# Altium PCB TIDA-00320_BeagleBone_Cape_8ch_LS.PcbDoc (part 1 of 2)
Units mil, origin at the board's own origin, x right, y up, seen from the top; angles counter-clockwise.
Board outline 6250 x 2150 mil, 2 copper layers (Top Layer, Bottom Layer), stack 62 mil thick; 116 components, 142 nets, 397 pads, 432 vias.
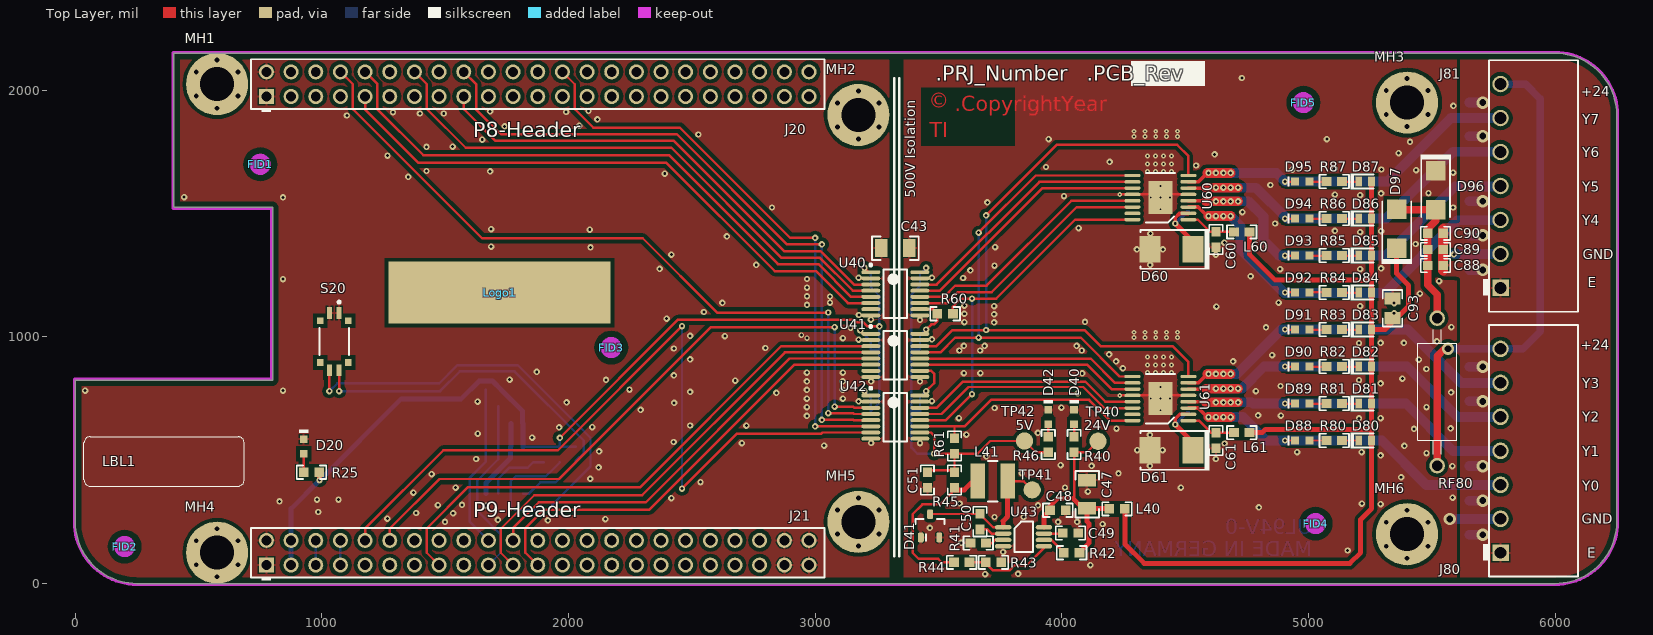
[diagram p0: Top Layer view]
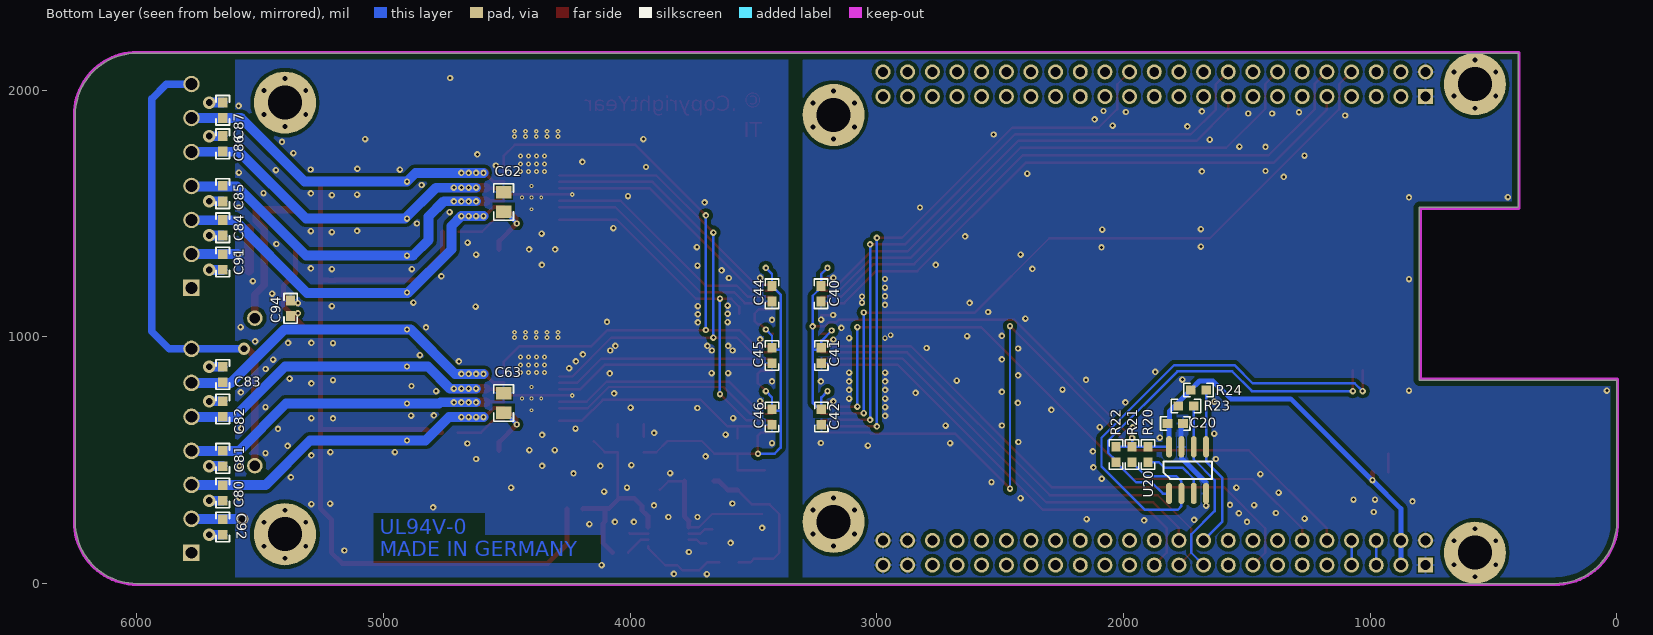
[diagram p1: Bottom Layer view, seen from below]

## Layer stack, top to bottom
Top Solder: solder mask 0.4, Solder Resist, Dk 3.5
Top Layer: signal copper 1.4
Dielectric1: core 59.2, FR-4, Dk 4.8
Bottom Layer: signal copper 1.4
Bottom Solder: solder mask 0.4, Solder Resist, Dk 3.5

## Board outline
250,0 cw(c250,250) 0,250 0,825 800,825 800,1525 400,1525 400,2150 6000,2150 cw(c6000,1900) 6250,1900 6250,250 cw(c6000,250) 6000,0

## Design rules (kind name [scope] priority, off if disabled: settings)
AcuteAngle [All] p1: minimum=3.00000000000000E+0001 checktracksonly=FALSE
AssemblyTestPointUsage [All] p1: valid=2
Clearance Clearance_BoardEdge_MountingHoles [OnCopper and InComponentClass('Mounting Holes') vs IsKeepOut] p1: gap=40
Clearance Clearance_BoardEdge_Poly [OnCopper and InPoly vs IsKeepOut] p2: gap=25
Clearance Clearance_BoardEdge [OnCopper and Not InComponentClass('Logo') and not InComponentClass('FiducialMark') and not InRegion(1000,500,4000,800) and Not IsKeepout vs IsKeepOut] p3: gap=24
Clearance Clearance_Poly [InPolygon] p4: gap=15
Clearance [All] p5: gap=7.87
ComponentClearance ComponentClearance_Shunt [InComponentClass('Header') vs InComponentClass('Shunt')] p1: gap=0 collisioncheckmode=3 verticalgap=0 showdistances=FALSE
ComponentClearance ComponentClearance_MountingHoles_FiducialMarks [InComponentClass('Mounting Holes') vs InComponentClass('FiducialMark')] p2: gap=50 collisioncheckmode=3 verticalgap=10 showdistances=FALSE
ComponentClearance ComponentClearance_Logo [InComponentClass('Logo')] p3: gap=50 collisioncheckmode=3 verticalgap=10 showdistances=FALSE
ComponentClearance ComponentClearance_ScrewToNut [(HasFootprint('NY PMS 440 0025 PH')) vs (HasFootprint('Keystone_1902C'))] p4: gap=5 collisioncheckmode=3 verticalgap=10 showdistances=FALSE
ComponentClearance ComponentClearance_MountingHoles [name like 'MH*'] p5: gap=0 collisioncheckmode=3 verticalgap=100000 showdistances=FALSE
ComponentClearance ComponentClearance_SmallPassives [HasFootprint('0201*') or HasFootprint('0402*') or HasFootprint('0508') or HasFootprint('0603*') or HasFootprint('0612') or HasFootprint('0805*') or HasFootprint('0815*') or HasFootprint('0830*') or HasFootprint('1206*') or HasFootprint('1210*') or HasFootprint('1808*') or HasFootprint('1812*') or HasFootprint('1825*') or HasFootprint('2010*') or HasFootprint('2220*') or HasFootprint('2225*') or HasFootprint('2512*') or HasFootprint('2728*') or HasFootprint('3518*') vs HasFootprint('0201*') or HasFootprint('0402*') or HasFootprint('0508') or HasFootprint('0603*') or HasFootprint('0612') or HasFootprint('0805*') or HasFootprint('0815*') or HasFootprint('0830*') or HasFootprint('1206*') or HasFootprint('1210*') or HasFootprint('1808*') or HasFootprint('1812*') or HasFootprint('1825*') or HasFootprint('2010*') or HasFootprint('2220*') or HasFootprint('2225*') or HasFootprint('2512*') or HasFootprint('2728*') or HasFootprint('3518*')] p6: gap=20 collisioncheckmode=3 verticalgap=10 showdistances=FALSE
ComponentClearance ComponentClearance_THtoSMT [IsThruComponent vs IsSMTComponent] p7: gap=90 collisioncheckmode=3 verticalgap=30 showdistances=FALSE
ComponentClearance ComponentClearance_THtoTH [IsThruComponent and not name like ('J8*') vs IsThruComponent and not name like ('J8*')] p8: gap=118.11 collisioncheckmode=3 verticalgap=30 showdistances=FALSE
ComponentClearance [All] p9: gap=38 collisioncheckmode=3 verticalgap=10 showdistances=FALSE
DiffPairsRouting [All] p1: maxlimit=100 minlimit=10 mostfreqgap=10 toplayer_minwidth=15 toplayer_maxwidth=15 toplayer_prefwidth=15 bottomlayer_minwidth=15 bottomlayer_maxwidth=15 bottomlayer_prefwidth=15 maxuncoupledlength=1000
FabricationTestPointUsage TestPointUsage [All] p1: valid=2 allowmultiple=FALSE
FabricationTestpoint Testpoint [All] p1: side=3 testpointundercomponent=TRUE minsize=40 maxsize=100 preferedsize=60 minholesize=0 maxholesize=40 preferedholesize=32 testpointgrid=1 allowsidetop=TRUE allowsidebottom=TRUE usegrid=TRUE gridtolerance=0.01
FanoutControl Fanout_LCC [IsLCC] p1: bgadir=Out bgaviamode=Centered fanoutstyle=Auto fanoutdirection=Alternating viagrid=1 // Fanout_LCC (Default Rule)
FanoutControl Fanout_BGA [IsBGA] p2: bgadir=Out bgaviamode=Centered fanoutstyle=Auto fanoutdirection=Alternating viagrid=1 // Fanout_BGA (Default Rule)
FanoutControl Fanout_Default [All] p4: bgadir=Out bgaviamode=Centered fanoutstyle=Auto fanoutdirection=Alternating viagrid=1 // Fanout_Default (Default Rule)
FanoutControl Fanout_Small [(CompPinCount < 5)] p5: bgadir=Out bgaviamode=Centered fanoutstyle=Auto fanoutdirection=OutThenIn viagrid=1 // Fanout_Small (Default Rule)
HoleSize [All] p1: absolutevalues=TRUE maxlimit=251 minlimit=7.6 maxpercent=80.000 minpercent=20.000
MinimumAnnularRing MinimumAnnularRing_InPoly [All] p1: minimumring=3
MinimumAnnularRing MinimumAnnularRing_ThermalPadVias [IsVia and InAnyComponent] p2: minimumring=3
MinimumAnnularRing [All] p3: minimumring=9
MinimumSolderMaskSliver MinimumSolderMaskSliver_Logo [InComponentClass('Logo') vs InComponentClass('Logo')] p1: minsoldermaskwidth=0.7
MinimumSolderMaskSliver [All] p2: minsoldermaskwidth=3.94
PlaneClearance [All] p1: clearance=10
PlaneConnect [All] p1: planeconnectstyle=Direct reliefexpansion=15 reliefentries=4 reliefconductorwidth=10 reliefairgap=5
PolygonConnect Polygon2Via [IsVia] p1: connectstyle=Direct reliefconductorwidth=10 reliefentries=4 polygonreliefangle="90 Angle" airgapwidth=10
PolygonConnect ThermalPolygonVia [IsVia AND (ViaDiameter = '50')] p2: connectstyle=Direct reliefconductorwidth=10 reliefentries=4 polygonreliefangle="90 Angle" airgapwidth=10
PolygonConnect ThermalPolygonPad [((ObjectKind = 'Pad') And (((Name Like 'U*') or (Name Like 'D*')) and (InComponentClass('Pg5 Cape Power Stages') or InComponentClass('Pg6 Cape Output')))) or ((ObjectKind = 'Pad') And (Name like 'U21*'))] p3: connectstyle=Direct reliefconductorwidth=10 reliefentries=4 polygonreliefangle="90 Angle" airgapwidth=10
PolygonConnect [All] p4: connectstyle=Relief reliefconductorwidth=10 reliefentries=4 polygonreliefangle="90 Angle" airgapwidth=5
RoutingVias ThermalPadVias [IsVia and InAnyComponent] p1: holewidth=7.87 width=19.68 viastyle="Through Hole" minholewidth=7.87 minwidth=10 maxholewidth=20 maxwidth=40
RoutingVias [All] p2: holewidth=16 width=34 viastyle="Through Hole" minholewidth=7.87 minwidth=20 maxholewidth=40 maxwidth=65
SMDToCorner [All] p1: distance=0
ShortCircuit ShortCircuit_MH_Via [name like 'MH*' vs IsVia] p1: allowed=TRUE
ShortCircuit [All] p2: allowed=FALSE
SilkToSilkClearance [All] p1: silktosilkclearance=0
SilkToSolderMaskClearance SilkscreenOverComponentPads [IsPad] p1: minsilkscreentomaskgap=0 clearancetoexposedcopper=TRUE
SolderMaskExpansion [All] p1: expansion=1.97
UnpouredPolygon [All] p1: allowunpoured=FALSE
Width [All] p1: maxlimit=100 minlimit=6 preferedwidth=10 checkconnectedcopper=TRUE
13 further rules are at their usual default settings.

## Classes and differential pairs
component class "Pg6 Cape Output": C80 C81 C82 C83 C84 C85 C86 C87 C88 C89 C90 C91 C92 C93 C94 D80 D81 D82 D83 D84 D85 D86 D87 D88 D89 D90 D91 D92 D93 D94 D95 D96 D97 J80 J81 R80 R81 R82 R83 R84 R85 R86 R87 RF80
component class "Pg5 Cape Power Stages": C60 C61 C62 C63 D60 D61 L60 L61 R60 R61 U60 U61
component class "Pg4 Cape Power Supply": C40 C41 C42 C43 C44 C45 C46 C47 C48 C49 C50 C51 D40 D41 D42 L40 L41 R40 R41 R42 R43 R44 R45 R46 TP40 TP41 TP42 U40 U41 U42 U43
component class Logo: Logo1
component class "Pg7 Hardware": FID1 FID2 FID3 FID4 FID5 LBL1 Logo1 MH1 MH2 MH3 MH4 MH5 MH6 ZZ1 ZZ2 ZZ3 ZZ4
component class FiducialMark: FID1 FID2 FID3 FID4 FID5
component class AssemblyNote: ZZ1 ZZ2 ZZ3 ZZ4
component class Label: LBL1
component class "Pg3 BB Connectors": C20 D20 J20 J21 R20 R21 R22 R23 R24 R25 S20 U20

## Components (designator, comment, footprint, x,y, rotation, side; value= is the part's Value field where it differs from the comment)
C20 "C0603C104K5RACTU" 0603 1790,649 r180 bottom
C40 "C0603C104K5RACTU" 0603 3226,1175 r270 bottom
C41 "C0603C104K5RACTU" 0603 3225,925 r270 bottom
C42 "C0603C104K5RACTU" 0603 3225,675 r270 bottom
C43 "202R18W102KV4E" 1206 3325,1360 r180 top
C44 "C0603C104K5RACTU" 0603 3425,1175 r270 bottom
C45 "C0603C104K5RACTU" 0603 3425,925 r270 bottom
C46 "C0603C104K5RACTU" 0603 3425,675 r270 bottom
C47 "C3216X7R1H105K" 1206 4103,362 r90 top
C48 "C0603C104K5RACTU" 0603 3984,297 r0 top
C49 "C0603C104K5RACTU" 0603 4035,205 r180 top
C50 "C0603C223K5RACTU" 0603 3668,251 r90 top
C51 "C0603C475K8PACTU" 0603 3455,420 r270 top
C60 "C0603C104K5RACTU" 0603 4625,1395 r270 top
C61 "C0603C104K5RACTU" 0603 4625,580 r270 top
C62 "CL21B104KCFSFNE" 0805_HV 4513.65,1547.09 r90 bottom
C63 "CL21B104KCFSFNE" 0805_HV 4513.65,732.09 r90 bottom
C80 "C1608X7R2A103M" 0603 5652,367.45 r270 bottom
C81 "C1608X7R2A103M" 0603 5652,507.45 r270 bottom
C82 "C1608X7R2A103M" 0603 5652,707.45 r90 bottom
C83 "C1608X7R2A103M" 0603 5652,847.45 r90 bottom
C84 "C1608X7R2A103M" 0603 5652,1443 r270 bottom
C85 "C1608X7R2A103M" 0603 5652,1581 r270 bottom
C86 "C1608X7R2A103M" 0603 5652,1783 r90 bottom
C87 "C1608X7R2A103M" 0603 5652,1919 r90 bottom
C88 "C1608X8R2A472K" 0603 5515,1290 r0 top
C89 "C1608X8R2A472K" 0603 5515,1355 r0 top
C90 "C1608X8R2A472K" 0603 5515,1420 r0 top
C91 "C1608X8R2A472K" 0603 5652,1304 r270 bottom
C92 "C1608X8R2A472K" 0603 5652,229 r270 bottom
C93 "CL21B105KBFNNNE" 0805_HV 5341,1116 r90 top
C94 "C0603C104K5RACTU" 0603 5377,1116 r90 bottom
D20 "LTST-C190KGKT" LED_LTST-C190_G 926,556 r90 top
D40 "LTST-C190KGKT" LED_LTST-C190_G 4050,675 r90 top
D41 "BAV70-V" SOT-23 3466,234 r90 top
D42 "LTST-C190KGKT" LED_LTST-C190_G 3945,675 r90 top
D60 "SMBJ48A-13-F" SMB 4444.51,1355 r180 top
D61 "SMBJ48A-13-F" SMB 4444.51,540 r180 top
D80 "CD0603-S0180" Diode_0603 5230,580 r0 top
D81 "CD0603-S0180" Diode_0603 5230,730 r0 top
D82 "CD0603-S0180" Diode_0603 5230,880 r0 top
D83 "CD0603-S0180" Diode_0603 5230,1030 r0 top
D84 "CD0603-S0180" Diode_0603 5230,1180 r0 top
D85 "CD0603-S0180" Diode_0603 5230,1330 r0 top
D86 "CD0603-S0180" Diode_0603 5230,1480 r0 top
D87 "CD0603-S0180" Diode_0603 5230,1630 r0 top
D88 "LB Q39G-L2N2-35-1" "LB Q39G_BLUE" 4974.94,580 r180 top
D89 "LB Q39G-L2N2-35-1" "LB Q39G_BLUE" 4974.94,730 r180 top
D90 "LB Q39G-L2N2-35-1" "LB Q39G_BLUE" 4974.97,880.03 r180 top
D91 "LB Q39G-L2N2-35-1" "LB Q39G_BLUE" 4974.94,1029.97 r180 top
D92 "LB Q39G-L2N2-35-1" "LB Q39G_BLUE" 4974.94,1180.29 r180 top
D93 "LB Q39G-L2N2-35-1" "LB Q39G_BLUE" 4975,1330 r180 top
D94 "LB Q39G-L2N2-35-1" "LB Q39G_BLUE" 4974.94,1479.99 r180 top
D95 "LB Q39G-L2N2-35-1" "LB Q39G_BLUE" 4975,1630 r180 top
D96 "SMAJ33CA" SMA 5516,1595 r270 top
D97 "MRA4003T3G" SMA 5358,1439 r90 top
FID1 "Fiducial" Fiducial10-20#1 750,1700 r0 top
FID2 "Fiducial" Fiducial10-20#1 200,150 r0 top
FID3 "Fiducial" Fiducial10-20#1 2173,957 r0 top
FID4 "Fiducial" Fiducial10-20#2 5029,243 r0 top
FID5 "Fiducial" Fiducial10-20#2 4980,1950 r0 top
J20 "SSHQ-123-D-08-F-LF" Major_SSHQ-123-D-08 1875,2025 r0 top
J21 "SSHQ-123-D-08-F-LF" Major_SSHQ-123-D-08 1875,125 r0 top
J80 "1844265" Phoenix_1844265 5779,538 r90 top
J81 "1844265" Phoenix_1844265 5779,1612 r90 top
L40 "BLM18KG601SN1D" 0603 4224,303 r180 top
L41 "SRN4026-680M" SRN4026 3720,415 r180 top
L60 "BLM18KG601SN1D" 0603 4730,1426 r180 top
L61 "BLM18KG601SN1D" 0603 4730,612 r180 top
LBL1 "Size: 0.65\" x 0.20 \"" Label_650x200 360,495 r0 top
Logo1 "Texas Instruments" TI_Stacked_SolderMask_Small 1720,1180 r0 top
MH1 "MTG_Pads" MTGP_4-40_PanHead 575,2025 r0 top
MH2 "MTG_Pads" MTGP_4-40_PanHead 3175,1900 r0 top
MH3 "MTG_Pads" MTGP_4-40_PanHead 5400,1950 r0 top
MH4 "MTG_Pads" MTGP_4-40_PanHead 575,125 r0 top
MH5 "MTG_Pads" MTGP_4-40_PanHead 3175,250 r0 top
MH6 "MTG_Pads" MTGP_4-40_PanHead 5400,200 r0 top
R20 "CRCW06035K62FKEA" 0603 1900,523.35 r90 bottom
R21 "CRCW06035K62FKEA" 0603 1965,523.35 r90 bottom
R22 "CRCW06035K62FKEA" 0603 2030,523.35 r90 bottom
R23 "CRCW06035K62FKEA" 0603 1746,720 r0 bottom
R24 "CRCW06035K62FKEA" 0603 1696,785 r0 bottom
R25 "CRCW0603453RFKEA" 0603 958,451 r0 top
R40 "CRCW06037K50FKEA" 0603 4050,564 r270 top
R41 "CRCW060386K6FKEA" 0603 3661,164 r0 top
R42 "CRCW060366K5FKEA" 0603 4040,125 r0 top
R43 "CRCW06032K00FKEA" 0603 3723,86 r180 top
R44 "CRCW06032K00FKEA" 0603 3594,86 r0 top
R45 "CRCW06031R00FKEA" 0603 3565,420 r90 top
R46 "CRCW06031K21FKEA" 0603 3945,564 r90 top
R60 "CRCW06032K00FKEA" 0603 3527,1094 r0 top
R61 "CRCW06032K00FKEA" 0603 3565,558 r90 top
R80 "CRCW060310K0FKEA" 0603 5105,580 r0 top
R81 "CRCW060310K0FKEA" 0603 5105,730 r0 top
R82 "CRCW060310K0FKEA" 0603 5105,880 r0 top
R83 "CRCW060310K0FKEA" 0603 5105,1030 r0 top
R84 "CRCW060310K0FKEA" 0603 5105,1180 r0 top
R85 "CRCW060310K0FKEA" 0603 5105,1330 r0 top
R86 "CRCW060310K0FKEA" 0603 5105,1480 r0 top
R87 "CRCW060310K0FKEA" 0603 5105,1630 r0 top
RF80 "47 Ohm" EMC2 5522,777 r270 top
S20 "CVS-02TB" SW_CVS-02B 1050,981 r270 top
TP40 "Pogo Pad" PogoPad 4147,577 r90 top
TP41 "Pogo Pad" PogoPad 3880,380 r90 top
TP42 "Pogo Pad" PogoPad 3849,578 r90 top
U20 "AT24C02D-SSHM-T" SOIC-8 1740,460 r90 bottom
U40 "ISO7140CCDBQ" DBQ0016A_N 3325,1175 r0 top
U41 "ISO7140CCDBQ" DBQ0016A_N 3325,925 r0 top
U42 "ISO7142CCDBQ" DBQ0016A_N 3325,675 r0 top
U43 "SM72485MM/NOPB" DGK0008A_N 3845,189.68 r0 top
U60 "DRV8803PWPR" PWP0016D_N 4400,1565 r180 top
U61 "DRV8803PWPR" PWP0016D_N 4400,750 r180 top
ZZ1 "This Assembly Note is for PCB labels only" AssemblyNoteLabel 185,3938 r0 top
ZZ2 "These assemblies are ESD sensitive, ESD precautions shall be observed." AssemblyNote 185,3829.11 r0 top
ZZ3 "These assemblies must be clean and free from flux and all contaminants. Use of no clean flux is not acceptable." AssemblyNote 185,3740.56 r0 top
ZZ4 "These assemblies must comply with workmanship standards IPC-A-610 Class 2, unless otherwise specified." AssemblyNote 185,3652 r0 top

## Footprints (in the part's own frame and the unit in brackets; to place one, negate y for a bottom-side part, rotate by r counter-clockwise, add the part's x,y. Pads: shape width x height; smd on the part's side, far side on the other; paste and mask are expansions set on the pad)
0603 [mm] "0603 from SM-752 data"
  rect 1x0.95 smd: 1(-0.8,0) 2(0.8,0)
  silkscreen extent -1.52,-0.69 1.52,0.69, body extent -0.87,-0.47 0.87,0.47, height 0.85
0805_HV [mil] "0805 with 30mil clearance between pads"
  rect 50x63 smd: 1(-40,0) 2(40,0)
  silkscreen extent -74,-40 74,40, body extent -43,-29 43,29, height 43
1206 [mm] "1206 from SM-752 data"
  rect 1.3x1.85 smd: 1(-1.45,0) 2(1.45,0)
  silkscreen extent -2.4,-1.21 2.4,1.21, body extent -1.7,-0.9 1.7,0.9, height 1.35
AssemblyNote [mil] "Assembly Note"
AssemblyNoteLabel [mil] "Assembly Note for PCB Labels"
DBQ0016A_N [mm] "SOP, 16-Leads, Body 4.9x3.9mm, Pitch 0.635mm, IPC Medium Density"
  oval 1.95x0.4 smd: 1(-2.525,2.222) 2(-2.525,1.587) 3(-2.525,0.953) 4(-2.525,0.318) 5(-2.525,-0.318) 6(-2.525,-0.953) 7(-2.525,-1.587) 8(-2.525,-2.222) 9(2.525,-2.222) 10(2.525,-1.587) 11(2.525,-0.953) 12(2.525,-0.318) 13(2.525,0.318) 14(2.525,0.953) 15(2.525,1.587) 16(2.525,2.222)
  silkscreen extent -2.65,-2.5 1.2,3.1, body extent -1.99,-2.5 2,2.5, height 1.76
DGK0008A_N [mm] "TSOP, 8-Leads, Body 3x3mm, Pitch 0.65mm, IPC Medium Density"
  oval 1.7x0.45 smd mask+0.05: 1(-2.1,0.975) 2(-2.1,0.325) 3(-2.1,-0.325) 4(-2.1,-0.975) 5(2.1,-0.975) 6(2.1,-0.325) 7(2.1,0.325) 8(2.1,0.975)
  silkscreen extent -0.95,-1.55 0.95,1.55, body extent -2.45,-1.5 2.45,1.5, height 0.94
Diode_0603 [mm] "Based on Bourns recommended land pattern Rev 10/09"
  rect 0.7x1 smd: 1(-0.65,0) 2(0.65,0)
  silkscreen extent -1.5,-0.8 0.9,0.8, body extent -0.9,-0.5 0.9,0.5, height 0.85
EMC2 [mm] "Welwyn"
  round 1.6 hole 1.1: 1(-7.6,0) 2(7.6,0)
  silkscreen extent -6.42,-2 6.42,2, body extent -8.02,-2 8.02,2, height 3.98
Fiducial10-20#1 [mm]
  round 1 smd paste-0.5 mask+0.5: 1(0,0)
  Top Layer keep-out circle w1.178: c0,0 r0.5
Fiducial10-20#2 [mm]
  round 1 smd mask+0.5: 1(0,0)
  Top Layer keep-out circle w1.178: c0,0 r0.5
Label_650x200 [mil] "Thermal Transfer Label"
  round 1 on Mech13: 0(0,0)
  silkscreen extent -325,-100 325,100, body extent -326,-101 326,101, height 1
"LB Q39G_BLUE" [mm] "OSRAM"
  rect 0.8x0.8 smd: 1(-0.75,0) 2(0.75,0)
  silkscreen extent 1.3,-0.5 1.52,0.5, body extent -0.85,-0.45 0.85,0.45, height 0.4
LED_LTST-C190_G [mm] "Lite-On"
  rect 0.8x0.8 smd: 1(-0.75,0) 2(0.75,0)
  silkscreen extent 1.37,-0.5 1.75,0.5, body extent -0.85,-0.45 0.85,0.45, height 0.9
Major_SSHQ-123-D-08 [mm] "Female Connector, 2.54mm, 23x2, TH"
  rect 1.55x1.55 hole 1.02: 1(-27.94,-1.27)
  round 1.55 hole 1.02: 2(-27.94,1.27) 3(-25.4,-1.27) 4(-25.4,1.27) 5(-22.86,-1.27) 6(-22.86,1.27) 7(-20.32,-1.27) 8(-20.32,1.27) 9(-17.78,-1.27) 10(-17.78,1.27) 11(-15.24,-1.27) 12(-15.24,1.27) 13(-12.7,-1.27) 14(-12.7,1.27) 15(-10.16,-1.27) 16(-10.16,1.27) 17(-7.62,-1.27) 18(-7.62,1.27) 19(-5.08,-1.27) 20(-5.08,1.27) 21(-2.54,-1.27) 22(-2.54,1.27) 23(0,-1.27) 24(0,1.27) 25(2.54,-1.27) 26(2.54,1.27) 27(5.08,-1.27) 28(5.08,1.27) 29(7.62,-1.27) 30(7.62,1.27) 31(10.16,-1.27) 32(10.16,1.27) 33(12.7,-1.27) 34(12.7,1.27) 35(15.24,-1.27) 36(15.24,1.27) 37(17.78,-1.27) 38(17.78,1.27) 39(20.32,-1.27) 40(20.32,1.27) 41(22.86,-1.27) 42(22.86,1.27) 43(25.4,-1.27) 44(25.4,1.27) 45(27.94,-1.27) 46(27.94,1.27)
  silkscreen extent -29.53,-2.85 29.53,2.57, body extent -29.46,-2.51 29.46,2.51, height 8.51
MTGP_4-40_PanHead [mm] "4-40 Mounting Hole, Plated, for Pan Head"
  round 6.4 hole 3.5: 1(0,0)
Phoenix_1844265 [mm] "TH, 7-Leads, Body 9.2x25.9, Pitch 3.5mm"
  rect 1.7x1.7 hole 1.2: 1(-10.5,0)
  round 1.7 hole 1.2: 2(-7,0) 3(-3.5,0) 4(0,0) 5(3.5,0) 6(7,0) 7(10.5,0)
  silkscreen extent -12.95,-8 12.95,1.8, body extent -12.95,-8 12.95,1.2, height 7.25
PogoPad [mil] "No Solder Paste"
  round 70 smd paste-35: 1(0,0)
PWP0016D_N [mm] "TSOP, 16-Leads, Body 5x4.4mm, Pitch 0.65mm, Exposed Pad, IPC Medium Density"
  oval 1.65x0.35 smd: 1(-2.875,2.275) 2(-2.875,1.625) 3(-2.875,0.975) 4(-2.875,0.325) 5(-2.875,-0.325) 6(-2.875,-0.975) 7(-2.875,-1.625) 8(-2.875,-2.275) 9(2.875,-2.275) 10(2.875,-1.625) 11(2.875,-0.975) 12(2.875,-0.325) 13(2.875,0.325) 14(2.875,0.975) 15(2.875,1.625) 16(2.875,2.275)
  rect 2.46x3.4 smd paste-1.5: 17(0,0)
  silkscreen extent -1.5,-2.55 1.5,2.55, body extent -3.21,-2.5 3.21,2.5, height 0.99
SMA [mm] "Molded Diode, 2-Leads, Body 4.3x2.6mm, IPC Medium Density, based on OnSemi component dimensions and land pattern"
  rect 2x2 smd: 1(-2,0) 2(2,0)
  silkscreen extent -3.66,-1.57 2.79,1.57, body extent -2.6,-1.3 2.6,1.3, height 2.42
SMB [mil] "Molded Diode, 2-Leads, Body 5.4x3.6mm, IPC Medium Density, based on OnSemi component dimensions"
  rect 85x107.99 smd: 1(-87.01,0) 2(87.01,0)
  silkscreen extent -155,-82 125,82, body extent -106,-71 106,71, height 91
SOIC-8 [mm] "duplicate of SO-8.  SOIC, 8-Leads, Body 5.0x4.0mm (max), Pitch 1.27mm, IPC Medium Density"
  oval 2.2x0.6 smd: 1(-2.4,1.905) 2(-2.4,0.635) 3(-2.4,-0.635) 4(-2.4,-1.905) 5(2.4,-1.905) 6(2.4,-0.635) 7(2.4,0.635) 8(2.4,1.905)
  silkscreen extent -0.9,-2.5 0.9,2.5, body extent -3,-2.45 3,2.45, height 1.63
SOT-23 [mm] "SOT23, 3-Leads, Body 2.9x1.3mm, Pitch 0.95mm, Lead Span 2.5mm, IPC Medium Density"
  rrect50% 1x0.6 smd: 1(-1.2,0.95) 2(-1.2,-0.95) 3(1.2,0)
  silkscreen extent -1.62,-1.5 0.7,1.5, body extent -1.16,-1.45 1.21,1.45, height 1
SRN4026 [mm] "SMD, 2-Leads, Body 4.2x4.2mm"
  rect 1.5x3.6 smd: 1(-1.525,0) 2(1.525,0)
  silkscreen extent -0.5,-2.1 0.5,2.1, body extent -2.1,-2.1 2.1,2.1, height 2.5
SW_CVS-02B [mm] "Copal Electronics"
  rect 1.2x0.5 smd: 1(-2.95,0.5) 2(-2.95,-0.5) 3(2.95,-0.5) 4(2.95,0.5)
  rect 0.7x0.7 smd: M1(-2.15,1.45) M2(-2.15,-1.45) M3(2.15,-1.45) M4(2.15,1.45)
  silkscreen extent -4.19,-1.5 1.4,1.5, body extent -2.15,-1.5 2.15,1.5, height 1.45
TI_Stacked_SolderMask_Small [mil]
  rect 900x250 smd paste-125 mask-125: 0(0,0)

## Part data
C20 C40 C41 C42 C44 C45 C46 C49 C60 C61: "CAP, CERM, 0.1 µF, 50 V, +/- 10%, X7R, 0603"
C43: "CAP, CERM, 1000pF, 2KV 10% X7R 1206"
C47: "CAP, CERM, 1uF, 50V, +/-10%, X7R, 1206"
C48 C94: "CAP, CERM, 0.1uF, 50V, +/-10%, X7R, 0603"
C50: "CAP, CERM, 0.022 µF, 50 V, +/- 10%, X7R, 0603"
C51: "CAP, CERM, 4.7 µF, 10 V, +/- 10%, X5R, 0603"
C62 C63: "CAP, CERM, 0.1 µF, 100 V, +/- 10%, X7R, 0805"
C80 C81 C82 C83 C84 C85 C86 C87: "CAP, CERM, 0.01 µF, 100 V, +/- 20%, X7R, 0603"
C88 C89 C90 C91 C92: "CAP, CERM, 4700 pF, 100 V, +/- 10%, X8R, 0603"
C93: "CAP, CERM, 1 µF, 50 V, +/- 10%, X7R, 0805"
D20 D40 D42: "LED, Green, SMD"
D41: "Diode, Switching, 70 V, 0.25 A, SOT-23"
D60 D61: "Diode, TVS, Uni, 48V, 600W, SMB"
D80 D81 D82 D83 D84 D85 D86 D87: "Diode, Switching, 90V, 0.1A, 0603 Diode"
D88 D89 D90 D91 D92 D93 D94 D95: "LED, Blue, SMD"
D96: "Diode, TVS, Bi, 33V, 400W, SMA"
D97: "Diode, Standard Recovery Rectifier, 300V, 1A, SMA"
FID1 FID2 FID3 FID4 FID5: "Fiducial mark.  There is nothing to buy or mount."
J20 J21: "Female Connector, 2.54mm, 23x2, TH"
J80 J81: "Header (Shrouded), 3.5 mm, 7x1, R/A, TH"
L40 L60 L61: "Ferrite Bead, 600 ohm @ 100 MHz, 1.3 A, 0603"
L41: "Inductor, Wirewound, Ferrite, 68uH, 0.35A, 0.852 ohm, SMD"
LBL1: library part THT-14-423-10, "Thermal Transfer Printable Labels, 0.650\" W x 0.200\" H - 10,000 per roll"
Logo1: library part TI_Logo, "Texas Instrument Corporate Signature"
MH1 MH2 MH3 MH4 MH5 MH6: library part "Mounting Hole (Imperial) with Pads", "PCB Mounting Hole"
R20 R21 R22 R23 R24: "RES, 5.62 k, 1%, 0.1 W, 0603"
R25: "RES, 453, 1%, 0.1 W, 0603"
R40: "RES, 7.50 k, 1%, 0.1 W, 0603"
R41: "RES, 86.6k ohm, 1%, 0.1W, 0603"
R42: "RES, 66.5k ohm, 1%, 0.1W, 0603"
R43 R44 R60 R61: "RES, 2.00 k, 1%, 0.1 W, 0603"
R45: "RES, 1.00, 1%, 0.1 W, 0603"
R46: "RES, 1.21 k, 1%, 0.1 W, 0603"
R80 R81 R82 R83 R84 R85 R86 R87: "RES, 10.0k ohm, 1%, 0.1W, 0603"
RF80: library part EMC2-47RKI, "RES, 47 ohm, 10%, 2W, Fusible, TH"
S20: "DIP Switch, SPST, 2Pos, Slide, SMT"
TP40 TP41 TP42: library part PogoPad, "Pad for Pogo Pin Connector"
U20: "I2C-Compatible (2-wire) Serial EEPROM 2-Kbit (256 x 8), SOIC-8"
U40 U41: "4242-VPK Small-Footprint and Low-Power Quad Channels Digital Isolators, DBQ0016A"
U42: "4242-V PK Small-Footprint and Low-Power Quad Channel Digital Isolator, DBQ0016A"
U43: "SolarMagic 100V, 150 mA Constant On-Time Buck Switching Regulator, DGK0008A"
U60 U61: "Quad Low-Side Driver IC, PWP0016D"
ZZ1: library part AssemblyNoteLabel
ZZ2 ZZ3 ZZ4: library part AssemblyNote

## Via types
v1: diameter 26, hole 12, Top Layer to Bottom Layer, tented both sides, 318 vias
v2: diameter 20, hole 8, Top Layer to Bottom Layer, tented both sides, 46 vias
v3: diameter 39.37, hole 19.68, Top Layer to Bottom Layer, 36 vias
v4: diameter 50, hole 28, Top Layer to Bottom Layer, tented both sides, 11 vias
v5: diameter 15.75, hole 7.87, Top Layer to Bottom Layer, 10 vias
v6: diameter 26, hole 12, Top Layer to Bottom Layer, 8 vias
v7: diameter 22, hole 12, Top Layer to Bottom Layer, tented both sides, 2 vias
v8: diameter 50, hole 28, Top Layer to Bottom Layer, 1 vias

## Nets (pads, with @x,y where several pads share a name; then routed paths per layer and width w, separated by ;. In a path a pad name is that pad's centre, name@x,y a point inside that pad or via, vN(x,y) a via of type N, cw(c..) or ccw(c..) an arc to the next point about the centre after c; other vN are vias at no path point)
24V_EXT: J80.7 J81.7 RF80.2 | length 2032.2
  Top Layer w30: RF80.2@5522,477.79 5522,922.19 5551.81,952 v8(5565.9,952)
  Bottom Layer w30: v8(5565.9,952) 5870,952 5940,1022 5940,1965 5881,2024 J81.7@5779,2024
+5V_ISO: C44.1 C45.1 C46.1 C51.1 R45.2 R46.1 R60.1 R61.1 TP42.1 U40.10 U40.16 U41.10 U41.16 U42.10 U42.16 | length 2241.2
  Top Layer w10: U41.16@3422.5,1012.5 U41.16@3424.41,1012.5 ; U42.10@3424.41,612.5 3469.5,612.5 3482,600 v1(3482,526.38) R61.1@3565,526.38 ; U41.10@3424.41,862.5 3470.5,862.5 3482,851 3482,812 v1(3450,780) ; U40.10@3424.41,1112.5 3477,1112.5 R60.1@3495.5,1094 3495.5,1064.86 3481.82,1051.18 3471.18,1051.18 v1(3450,1030) ; C51.1@3455,460 3565,460 R61.1@3565,526.38 ; R46.1@3945,532.5 3894.5,532.5 TP42.1@3849,578 3710,578 3658.38,526.38 R61.1@3565,526.38
  Bottom Layer w10: 3394,700 3426.38,700 3425,698.62 3425,755 v1(3450,780) ; v1(3450,1030) 3425,1005 3425,948.62 3390,948.62 ; v1(3450,1280) 3425,1255 C44.1@3425,1206.5 3390,1171.5 3390,948.62 ; v1(3482,526.38) 3414.62,526.38 3390,551 3390,948.62
+24V_EMI1: C60.1 L60.2 U60.1 | length 202.1
  Top Layer w10: U60.1@4513.19,1475.43 4551.31,1475.43 4600.24,1426.5 C60.1@4625,1426.5 L60.2@4695,1426.5
+24V_EMI2: C61.1 L61.2 U61.1 | length 205.4
  Top Layer w10: U61.1@4513.19,660.43 4556.01,660.43 4604.44,612 L61.2@4698.5,612
+24V_FIELD: C93.1 C94.1 D80.2 D81.2 D82.2 D83.2 D84.2 D85.2 D86.2 D87.2 D97.1 L40.1 L60.1 L61.1 | length 4239.9
  Top Layer w20: L40.1@4255.5,303 4255.5,160.5 4334,82 5168,82 5211.51,125.51 5211.51,259.51 5255.59,303.59 D80.2@5255.59,580 D81.2@5255.59,730 D82.2@5255.59,880 D83.2@5255.59,1030 ; L60.1@4761.5,1426 4761.5,1333.5 4865,1230 5196.34,1230 5197.21,1229.13 5222.79,1229.13 5223.66,1230 5255.59,1230 ; L61.1@4764.5,612 4813,612 4826,625 5251.46,625 ; D87.2@5255.59,1630 D86.2@5255.59,1480 D85.2@5255.59,1330 D84.2@5255.59,1180 D83.2@5255.59,1030 ; D97.1@5358,1360.26 5358,1257 5406,1209 5406,1123.91 5341,1058.91 5312.09,1030 D83.2@5255.59,1030
  other v1: 5348,1096
/FAULT0: R61.2 U42.11 U61.16 | length 989
  Top Layer w10: U42.11@3424.41,637.5 3605.5,637.5 3713,745 4110.87,745 4195.43,660.43 U61.16@4286.81,660.43 ; R61.2@3565,589.5 3565,636.5
/FAULT1: R60.2 U42.12 U60.16 | length 1545.3
  Top Layer w10: U42.12@3424.41,662.5 3530.5,662.5 v1(3636,768) ; R60.2@3558.5,1094 3558.5,1122.5 3591,1155 v1(3636,1155) 3734,1155 4054.43,1475.43 U60.16@4286.81,1475.43
  Bottom Layer w10: v1(3636,768) v1(3636,1155)
AIN0: J21.39
AIN1: J21.40
AIN2: J21.37
AIN3: J21.38
AIN4: J21.33
AIN5: J21.36
AIN6: J21.35
CLKOUT2: J21.41
DGND: C20.2 C40.2 C41.2 C42.2 C43.2 D20.2 J20.1 J20.2 J21.1 J21.2 J21.43 J21.44 J21.45 J21.46 S20.1 S20.2 U20.4 U20.7 U40.2 U40.8 U41.2 U41.8 U42.2 U42.8 | length 541.1
  Top Layer w10: v1(3176,739) 3177.5,737.5 U42.2@3225.59,737.5 ; v1(3176,989) 3177.5,987.5 U41.2@3225.59,987.5 ; v1(3176,1240) 3178.5,1237.5 U40.2@3225.59,1237.5 ; v1(3177.36,1089) 3178.86,1087.5 U40.8@3225.59,1087.5 3225.59,1070.41 v1(3226,1070)
  Bottom Layer w20: U20.4@1665,365.51 1665,409 1765,509 U20.7@1765,554.49 ; U20.7@1766.38,555.87 C20.2@1766.38,649
  other v1: 1499,250 1916,256 1713,258 2149,261 1265,263 1532,285 1382,286 985,290 1665,316 1470,318 1568,319 828,333 980,340 1067,340 2417,346 1371,369 1542,389 2535,411 2088,425 1445,444 2122,471 1625,505 2124,536 3036,559 2703,569 3227,570 2426,574 1852,592 1631.73,607.64 1962,633 2096,634 2721,640 2493,641 2966,680 2292,704 2966,715 2428,733 1992,735 1631,738 2966,750 3112,750 2843,773 2493,777 40,782 842,782 2966,785 3112,785 2247,786 2966,820 3112,820 3227,820 2676,823 2152,826 1761,827 2427,844 2966,855 3112,855 1871,858 2493,909 2427,953 2798,955 3112,995 2634,1003 2493,1004 3144,1037 2398,1074 2549,1101 2967,1130 2624,1138 3060,1139 3060,1164 2967,1165 2967,1200 842,1234 2967,1235 2369,1276 2761,1292 2417,1334 2089,1363 1686,1366 2642,1408 2086,1435 1686,1437 2825,1525 842,1566 441,1567 1350,1649 2390,1662 1682,1671 1424,1673 1266,1735 1424,1771 1530,1772 1650,1800 2526,1821 1741,1854 2044,1857 2117,1882 1101,1898 1397,1906 1494,1906 1288,1911 1990,1912 1682,1915 2081,1916
  other v7: 2967,995 2944,1007
EHRPWM1A: J21.14
EHRPWM1B: J21.16
EHRPWM2A: J20.19
EHRPWM2B: J20.13
GND_EARTH: C80.2 C81.2 C82.2 C83.2 C84.2 C85.2 C86.2 C87.2 C88.2 C89.2 C90.2 C91.2 C92.2 J80.1 J81.1 | length 715.3
  Top Layer w40: 5546.5,1269 C89.2@5546.5,1355 C90.2@5546.5,1437
  Bottom Layer w40: C80.2@5652,335.95 v4(5707,336) ; C87.2@5652,1950 v4(5707,1950) ; C81.2@5652,475.95 v4(5707,476) ; C82.2@5652.06,739 v4(5707,739) ; C83.2@5652.06,879 v4(5707,879) ; C92.2@5652.5,198 v4(5707,198) ; C91.2@5652.5,1272 v4(5707,1272) ; C84.2@5652.5,1412 v4(5707,1412) ; C85.2@5652.5,1550 v4(5707,1550) ; C86.2@5652.5,1814 v4(5707,1814)
GND_ISO: C43.1 C44.2 C45.2 C46.2 C47.2 C48.2 C49.1 C51.2 C60.2 C61.2 C62.2 C63.2 C91.1 C92.1 C93.2 C94.2 D40.2 D41.1 D41.2 D42.2 D60.2 D61.2 D96.1 J80.2 J81.2 R41.1 R43.1 U40.9 U40.15 U41.9 U41.15 U42.9 U42.15 U43.4 U60.5 U60.12 U60.17 U61.5 U61.12 U61.17 | length 950
  Top Layer w10: v2@4235,762.8 U61.5@4513.19,762.8 ; v2@4235,1577.8 U60.5@4513.19,1577.8
  Bottom Layer w40: v4@5573,262.41 J80.2@5779,262.41 ; v1@5591.41,1336.41 J81.2@5779,1336.41
  other v1: 3689,38 3823,39 4116,75 3762,128 5159,134 3593,165 3465,226 4166,241 3985,250 4062,250 3727,270 3845,270 4799,309 3903.63,316.99 5293,322 5217,324 3586.01,324.63 5585,348 4106,373 4013,389 4483,389 5376,431 4230,447 3838,448 5584,476 4121,477 4357,477 3995,480 4625,505 3694,516 5293,520 5479,529 4954,533 5216,533 4306,541 4409,541 5389,558 4660,568 3425,569 4357,603 3613,604 3903,611 5428,627 4222,628 5577,629 5205,670 3583,671 5293,671 4888,681 4796,682 3728,712 3998,713 5479,715 3473,740 4065,771 5579,775 4787,780 4887,801 5293,812 3425,820 5205,825 5381,831 4083,852 3603,853 3670,853 5478,870 4248,873 4220,901 4695,901 5448,908 4853,926 4192,929 3585,945 3669,945 4081,945 3603,964 3687,964 4060,964 5205,975 5293,976 5387,976 5521,982 3473,990 4828,1039 5580,1040 3726,1059 3605,1060 4094,1061 3425,1069 3726,1092 3605,1094 4627,1123 3726,1125 5210,1125 3605,1127 5348,1137 4879.23,1138.77 5452,1175.63 5530,1226 3600,1239 3473,1240 4766,1246 3629,1270 4885,1275 5210,1275 5295,1278 3727,1289 4358,1292 4625,1334 5590,1335 4304.74,1355 4410,1355 3730,1364 5435,1377 4659,1382 4359,1419 5210,1425 5295,1429 5107,1430 4068,1441 4865,1460 4732,1506 5587,1525 3698,1546 4009,1571 5210,1575 5107,1577 5295,1582 5487,1583 4846,1616 5587,1666 5437,1676 4934,1678 5296,1679 5106,1682 3936,1689 4545,1695 4194,1710 4620,1740 5366,1745 5412,1791 3947,1802 5075,1802 5588,1937 4730,2050
  other v2: 4235,763 4348,855 4380,855 4412,855 4444,855 4348,887 4380,887 4412,887 4444,887 4348,919 4380,919 4412,919 4444,919 4293,997 4337,997 4381,997 4425,997 4469,997 4293,1019 4337,1019 4381,1019 4425,1019 4469,1019 4235,1578 4348,1670 4380,1670 4412,1670 4444,1670 4348,1702 4380,1702 4412,1702 4444,1702 4348,1734 4380,1734 4412,1734 4444,1734 4293,1812 4337,1812 4381,1812 4425,1812 4469,1812 4293,1834 4337,1834 4381,1834 4425,1834 4469,1834
  other v4: 5573,262
  other v5: 4400,702.76 4360.63,750 4400,750 4439.37,750 4400,797.24 4400,1517.76 4360.63,1565 4400,1565 4439.37,1565 4400,1612.24
GNDA_ADC: J21.34
GPIO0_7: J21.42
GPIO0_26: J20.14 U40.4 | length 2276.8
  Top Layer w10: J20.14@1375,2075 1425,2025 1425,1925 1583,1767 2417,1767 2862,1322 3018,1322 3152.5,1187.5 U40.4@3225.59,1187.5
GPIO0_27: J20.17 U40.3 | length 1996.3
  Top Layer w10: J20.17@1575,1975 1575,1924 1704,1795 2427,1795 2874,1348 3022,1348 3157.5,1212.5 U40.3@3225.59,1212.5
GPIO1_12: J20.12
GPIO1_13: J20.11
GPIO1_14: J20.16
GPIO1_15: J20.15
GPIO1_16: J21.15 U41.3 | length 2276.2
  Top Layer w10: J21.15@1475,75 1425,125 1425,224 1591,390 2290,390 2862.5,962.5 U41.3@3225.59,962.5
GPIO1_17: J21.23 U41.6 | length 1845.7
  Top Layer w10: J21.23@1875,75 1825,125 1825,225 1900,300 2328,300 2915.5,887.5 U41.6@3225.59,887.5
GPIO1_28: J21.12 U42.3 | length 2661.9
  Top Layer w10: J21.12@1275,175 1275,223 1476,424 1961,424 2577,1040 v1(3079,1040) ; v1(3079,717) 3154,717 3158.5,712.5 U42.3@3225.59,712.5
  Bottom Layer w10: v1(3079,717) v1(3079,1040)
GPIO1_29: J20.26 U42.6 | length 2353.8
  Top Layer w10: J20.26@1974.37,2075 2025,2024.38 2025,1924 2100,1849 2451,1849 2898,1402 v1(3000,1402) ; v1@3000,637.5 U42.6@3225.59,637.5
  Bottom Layer w10: v1(3000,637) v1(3000,1402)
